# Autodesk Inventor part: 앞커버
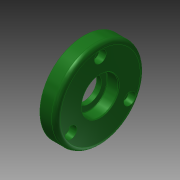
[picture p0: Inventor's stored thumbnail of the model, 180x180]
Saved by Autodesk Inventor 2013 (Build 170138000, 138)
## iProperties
Created: 2015-11
Part Number: 앞커버
Material: 알루미늄 6061
Document SubType Name: Modeling
Designer: mduedu
Density: 1 g/cm^3
Author: mduedu
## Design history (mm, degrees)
sketch "스케치5"
  geometry: C1 r 30 at (0, 0); 2 further points
  constraints: 2 coincident, 1 centre point
  dimensions: "d66" = 60 diameter of C1
extrude "돌출2" new body sketch "스케치5" distance "d67" = 11; taper "d68" = 0 deg
sketch "스케치6"
  geometry: C1 r 16 at (0, 0); 1 further point
  constraints: 1 centre point, 1 coincident
  dimensions: "d69" = 32 diameter of C1
extrude "돌출3" join sketch "스케치6" distance "d70" = 3; taper "d71" = 0 deg
hole "구멍7" diameter "d98" = 27; stored, may be unused: countersink angle "d102" = 90 deg, drill point angle "d104" = 0 deg; dims "d99" = 6, "d100" = 4, "d101" = 2, "d103" = 3, "d143" = 10, "d144" = 10
hole "구멍8" diameter "d107" = 25; stored, may be unused: countersink angle "d111" = 90 deg, drill point angle "d113" = 0 deg; dims "d105" = 10, "d106" = 10, "d108" = 6, "d109" = 4, "d110" = 2, "d112" = 7.7
hole "구멍9" diameter "d116" = 17; stored, may be unused: countersink angle "d120" = 90 deg, drill point angle "d122" = 0 deg; dims "d114" = 10, "d115" = 10, "d117" = 6, "d118" = 4, "d119" = 2, "d121" = 7.7
chamfer "모따기2" distance "d123" = 0.6; stored, may be unused: second distance "d124" = 2, angle "d125" = 30 deg
fillet "모깎기11" dims "d126" = 0.3
fillet "모깎기13" dims "d128" = 3
fillet "모깎기14" dims "d129" = 3
fillet "모깎기15" dims "d130" = 0.3
sketch "스케치8" dims "d131" = 46
  geometry: 3 further points
  constraints: 2 vertical alignment, 1 coincident, 2 other
hole "구멍10" sketch "스케치8" at (0, 23) diameter "d132" = 4.5; stored, may be unused: countersink angle "d136" = 90 deg, drill point angle "d138" = 0 deg; dims "d133" = 6, "d134" = 8, "d135" = 4.6, "d137" = 7.7
node "솔리드2"
pattern_circular "원형 패턴4" dims angle "d140" = 360 deg
